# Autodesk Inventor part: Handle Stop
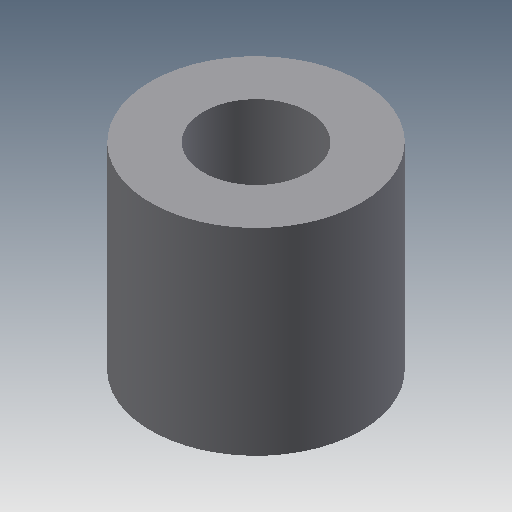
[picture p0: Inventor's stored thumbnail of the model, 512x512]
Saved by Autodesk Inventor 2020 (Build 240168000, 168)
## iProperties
Created: 2002-02
Part Number: Handle Stop
Document SubType Name: Modeling
Designer: ***
Density: 1 g/cm^3
Material: Generic
Appearance: Default
Control State: 0
Master: False
Checked Out: False
Shininess: 77.0
Length Units: 11269
Angle Units: 11279
Time Units: 11290
Mass Units: 11283
Length Display Precision: 3
Angle Display Precision: 2
Compacted: True
Density: 0.0
Volumn: 0.0
Area: 0.0
PropertySet Name: Model Information
Author: ***
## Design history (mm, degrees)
sketch "Sketch1"
  geometry: L1 (0, 0)-(0, -2); L2 (0, -2)-(8, -2); L3 (8, -2)-(8, 13); L4 (8, 13)-(4, 13); L5 (4, 13)-(4, 0); L6 (4, 0)-(0, 0)
  constraints: 12 end point, 4 parallel, 1 perpendicular, 1 vertical
  dimensions: "d0" = 16 diameter of L3 L1; "d1" = 8 diameter of L5 L1; "d2" = 2 distance of L1.start L1.end; "d3" = 15 distance of L2.end L3.end
revolve "Revolution1" sketch "Sketch1" stored, may be unused: angle "d4" = 90 deg
body "Solid1"
